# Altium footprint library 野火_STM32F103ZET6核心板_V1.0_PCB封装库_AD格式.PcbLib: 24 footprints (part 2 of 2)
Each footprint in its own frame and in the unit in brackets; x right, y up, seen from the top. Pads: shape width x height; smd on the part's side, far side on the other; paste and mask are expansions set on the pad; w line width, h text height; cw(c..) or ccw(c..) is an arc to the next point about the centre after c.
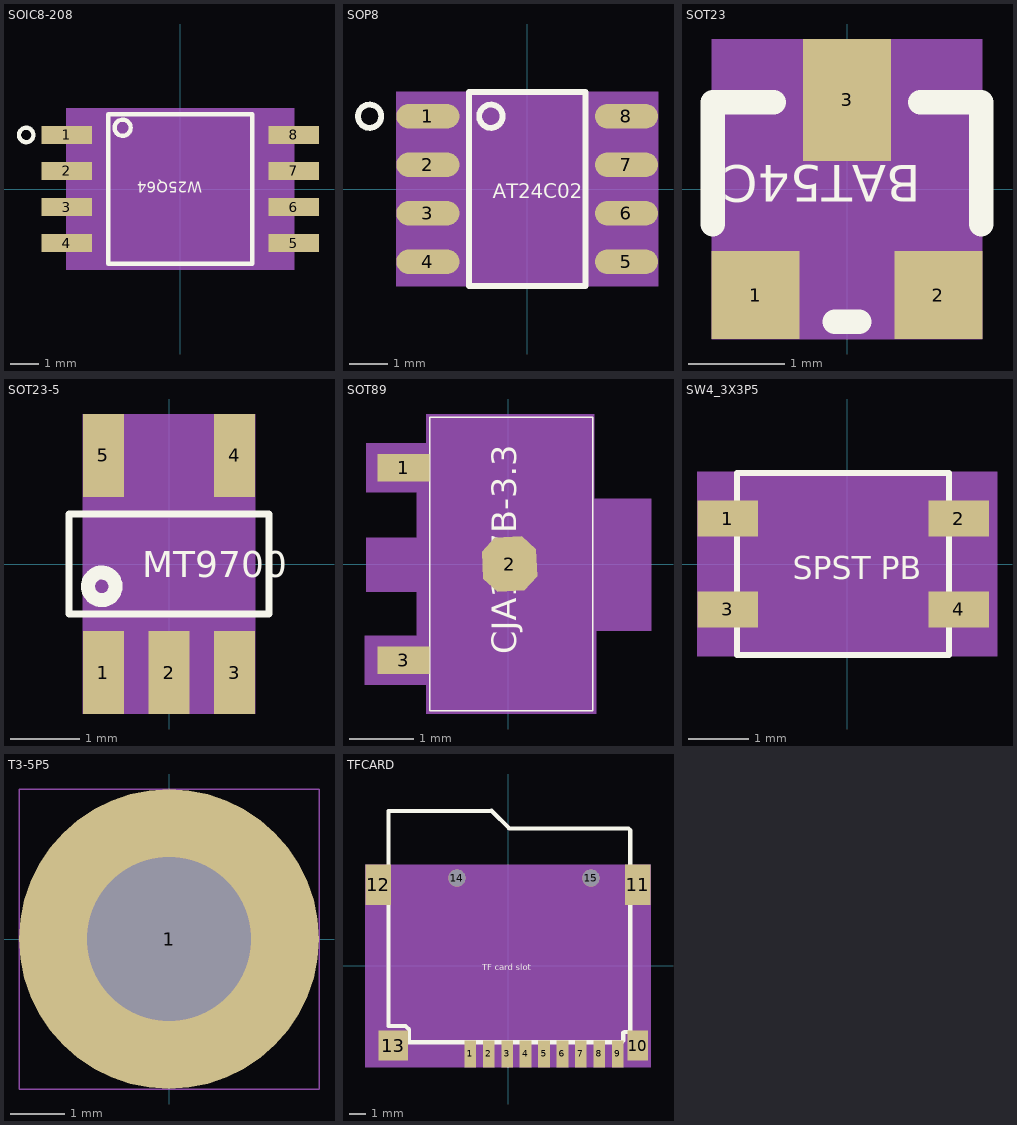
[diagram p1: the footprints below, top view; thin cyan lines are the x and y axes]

## SOIC8-208 [mil] "SOIC8-208"
pads (8):
  rect 70x25 smd: 1(-157.48,75) 2(-157.48,25) 3(-157.48,-25) 4(-157.48,-75) 5(157.48,-75) 6(157.48,-25) 7(157.48,25) 8(157.48,75)
Top Overlay:
  circle w6: c-80,85 r11.18
  circle w6: c-213.78,75 r10
  lines w6: -100,-103.94 100,-103.94 100,103.94 -100,103.94 -100,-103.94
  text ".Designator" at -215,-33.5 h30
  text "W25Q64" at 30.25,9.75 h15
Mechanical 9:
  text "5" at 157.48,-83 h20
  text "2" at -157.48,17 h20
  text "6" at 157.48,-33 h20
  text "1" at -157.48,67 h20
  text "3" at -157.48,-33 h20
  text "8" at 157.48,67 h20
  text "7" at 157.48,17 h20
  text "4" at -157.48,-83 h20
Mechanical 11:
  region: -158.2,-112 158.2,-112 158.2,112 -158.2,112
Mechanical 12:
  lines w6: -100,-103.94 100,-103.94 100,103.94 -100,103.94 -100,-103.94
Mechanical 13:
  pour cut-out: -158.2,-112 158.2,-112 158.2,112 -158.2,112

## SOP8 [mil] "SOP8"
pads (8):
  oval 65x25 smd: 1(-102.36,75) 2(-102.36,25) 3(-102.36,-25) 4(-102.36,-75) 5(102.36,-75) 6(102.36,-25) 7(102.36,25) 8(102.36,75)
Top Overlay:
  circle w6: c-37.36,75 r12
  circle w6: c-162.36,75 r12
  lines w6: -60,-100 -60,100 60,100 60,-100 -60,-100
  text "AT24C02" at -35.3,-9.75 h15
Mechanical 9:
  text "5" at 102.36,-65 h25
  text "6" at 102.36,-15 h25
  text "8" at 102.36,85 h25
  text "7" at 102.36,35 h25
  text "1" at -102.36,85 h25
  text "2" at -102.36,35 h25
  text "3" at -102.36,-15 h25
  text "4" at -102.36,-65 h25
Mechanical 11:
  region: -134.86,-100 134.86,-100 134.86,100 -134.86,100

## SOT23 [mil] "SOT23"
pads (3):
  rect 36x36 smd: 1(-37.5,-43.5) 2(37.5,-43.5)
  rect 36x50 smd: 3(0,36.5)
Top Overlay:
  lines w10: -55,-14.5 -55,35.5 -30,35.5 ; -5,-54.5 5,-54.5 ; 30,35.5 55,35.5 55,-14.5
  text "BAT54C" at 30.25,9.75 h15
Mechanical 9:
  text "3" at 0,26.5 h25
  text "2" at 37.5,-53.5 h25
  text "1" at -37.5,-53.5 h25
Mechanical 11:
  region: -55.5,-61.5 55.5,-61.5 55.5,61.5 -55.5,61.5

## SOT23-5 [mil] "SOT23-5"
pads (5):
  rect 23.62x47.24 smd: 1(-37.4,-62.01) 2(0,-62.01) 3(37.4,-62.01) 4(37.4,62.01) 5(-37.4,62.01)
Top Overlay:
  circle w8: c-38.4,-12.79 r7.87
  lines w4: -57.09,-28.54 57.09,-28.54 57.09,18.7 57.09,28.54 -57.09,28.54 -57.09,18.7 -57.09,-28.54
  text "MT9700" at -15.25,-7.5 h15
Mechanical 9:
  text "3" at 37.4,-52.01 h25
  text "4" at 37.4,72.01 h25
  text "5" at -37.4,72.01 h25
  text "1" at -37.4,-52.01 h25
  text "2" at 0,-52.01 h25
Mechanical 11:
  region: -49.21,-85.63 49.21,-85.63 49.21,85.63 -49.21,85.63

## SOT89 [mil] "SOT89"
pads (3):
  rect 32x17 smd: 1(-64,59) 3(-64,-59)
  oct 33.3x33.3 smd rot 93: 2(1,0)
Top Overlay:
  lines w1: -48,-90 52,-90 52,90 -48,90 -48,-90
  text ".Designator" at 135,-25.5 h30
  text "CJA117B-3.3" at 5,-55.5 h15
Mechanical 9:
  text "2" at -93,-28 h25
  text "3" at -92,-86 h25
  text "1" at -91,29 h25
Mechanical 11:
  region: 2,-92 54,-92 54,-41 88,-41 88,40 53,40 53,92 -50,92 -50,74 -87,74 -87,44 -56,44 -56,16 -87,16 -87,-17 -56,-17 -56,-44 -88,-44 -88,-74 -50,-74 -50,-92
Mechanical 12:
  lines w1: -48,-90 52,-90 52,90 -48,90 -48,-90

## SW4_3X3P5 [mil] "SW4_3X3P5"
pads (4):
  rect 39.37x23.62 smd: 1(-77.5,29.53) 2(72.5,29.53) 3(-77.5,-29.53) 4(72.5,-29.53)
Top Overlay:
  lines w3.94: -71.4,-59.06 -71.4,59.06 66.4,59.06 66.4,-59.06 -71.4,-59.06
  text "SPST PB" at -35.3,-9.75 h15
Mechanical 9:
  text "1" at -77.5,39.53 h25
  text "2" at 72.5,39.53 h25
  text "4" at 72.5,-19.53 h25
  text "3" at -77.5,-19.53 h25
Mechanical 11:
  region: -97.5,-60 97.5,-60 97.5,60 -97.5,60

## T3-5P5 [mm] "T3-5P5"
pads (1):
  round 5.5 / inner round 1.524 / far side round 5.5 hole 3: 1(0,0)
Top Overlay:
  text "3.0mm" at -0.64,-0.184 h0.38
Mechanical 9:
  text "1" at -0.254,0 h0.64
Mechanical 11:
  lines w0.025: -2.75,-2.75 2.75,-2.75 2.75,2.75 -2.75,2.75 -2.75,-2.75

## TFCARD [mil] "TFCARD"
pads (15):
  rect 27.56x62.99 smd: 1(-88.58,-206.83) 2(-45.27,-206.83) 3(-1.97,-206.83) 4(41.34,-206.83) 5(84.65,-206.83) 6(127.95,-206.83) 7(171.26,-206.83) 8(214.57,-206.83) 9(257.88,-206.83)
  rect 47.24x70 smd: 10(305.12,-187.14)
  rect 60x95 smd: 11(305.12,190.81) 12(-305.12,190.81)
  rect 70x70 smd: 13(-269.68,-187.14)
  round 40 / inner round 60 / far side round 40 hole 40: 14(-120.08,206.56) 15(194.88,206.56)
Top Overlay:
  lines w10: -280.88,-141.19 -280.88,364.04 -38.88,364.81 3.12,322.81 283.12,322.81 287.12,318.81 287.12,-153.19 289.12,-155.19 273.12,-155.19 271.12,-157.19 271.12,-175.19 267.12,-179.19 -232.88,-179.19 -232.88,-149.19 -240.88,-141.19 -280.88,-141.19
  text "TF card slot" at -60.55,-9.75 h15
Mechanical 9:
  text "3" at -1.97,-216.83 h25
  text "8" at 214.57,-216.83 h25
  text "7" at 171.26,-216.83 h25
  text "5" at 84.65,-216.83 h25
  text "2" at -45.27,-216.83 h25
  text "1" at -88.58,-216.83 h25
  text "4" at 41.34,-216.83 h25
  text "9" at 257.88,-216.83 h25
  text "14" at -120.08,186.56 h25
  text "15" at 194.88,186.56 h25
  text "11" at 305.12,170.81 h25
  text "13" at -269.68,-207.14 h25
  text "12" at -305.12,170.81 h25
  text "6" at 127.95,-216.83 h25
  text "10" at 305.12,-207.14 h25
Mechanical 10:
  region: 335.12,238.31 335.12,-238.32 -335.12,-238.32 -335.12,238.31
